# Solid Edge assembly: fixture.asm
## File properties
Author: Robert a Rhodes jr
Template: NORMENG.ASM
Last saved by: Robert a Rhodes jr
Revision: 7
Application: Solid Edge
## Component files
endplate.par
disk.par
support pin.par
spacer.par
bolt.par
center pin.par
nut.par
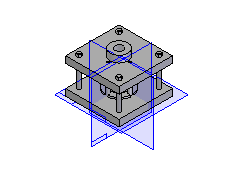
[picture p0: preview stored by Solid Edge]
